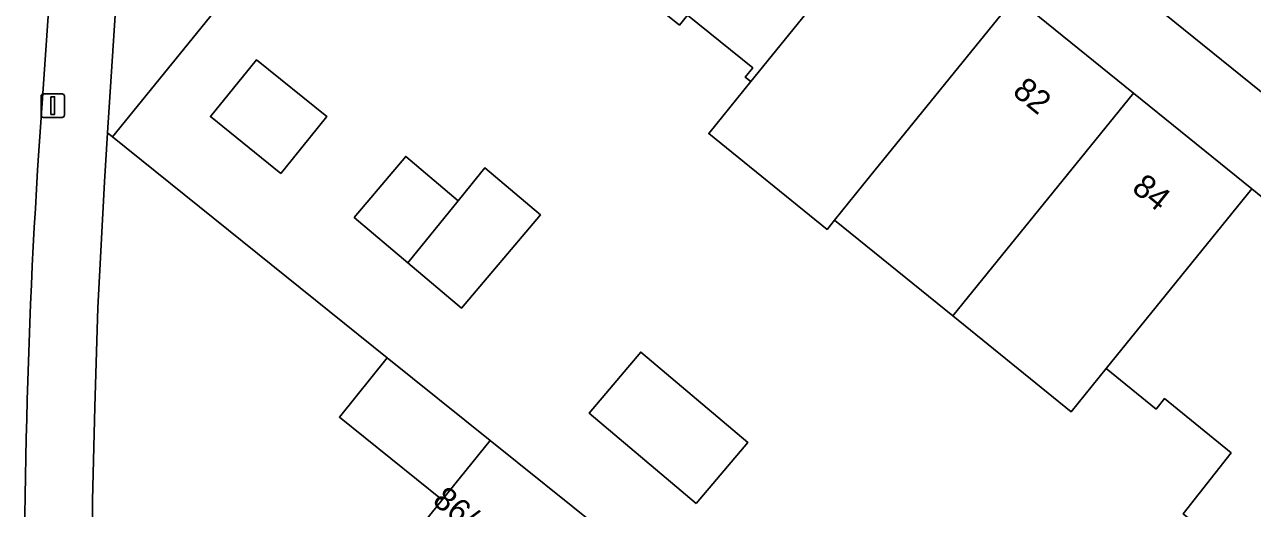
# Model space of a CAD drawing. Extents: x 160157 to 160921, y 381516 to 382045.
# Drawn here: x 160534.6 to 160586.6, y 381662.9 to 381683.4 of the extents above; entities that cross this region are included whole.
import ezdxf

# ---------------------------------------------------------------- set-up
doc = ezdxf.new("R2010")
doc.units = 0
for name, color, linetype in [('IMGEO_Erf', 7, 'Continuous'), ('IMGEO_Fietspad_gesloten', 7, 'Continuous'), ('IMGEO_Groenvoorziening', 7, 'Continuous'), ('IMGEO_Lichtmast', 7, 'Continuous'), ('IMGEO_Pand', 7, 'Continuous'), ('IMGEO_Pand_nummerreeks', 7, 'Continuous'), ('IMGEO_Voetpad_open', 7, 'Continuous')]:
    doc.layers.add(name, color=color, linetype=linetype)

msp = doc.modelspace()

# ---------------------------------------------------------------- linework, layer by layer
at = {"layer": 'IMGEO_Erf'}
for points in [[(160558.545, 381703.514), (160556.409, 381700.887), (160561.559, 381696.713), (160566.569, 381692.651), (160571.58, 381688.589), (160576.591, 381684.528), (160581.601, 381680.467), (160586.612, 381676.405), (160591.761, 381672.231), (160587.997, 381667.587), (160590.45, 381665.598), (160595.868, 381673.258), (160595.937, 381673.356), (160593.737, 381675.072)], [(160545.487, 381677.061), (160542.498, 381679.466), (160544.447, 381681.872), (160547.428, 381679.473), (160545.669, 381677.286)], [(160553.139, 381671.349), (160550.863, 381673.273), (160548.591, 381675.194), (160550.775, 381677.778), (160552.994, 381675.903), (160554.122, 381677.294), (160556.479, 381675.302)], [(160563.07, 381663.071), (160558.538, 381666.9), (160560.727, 381669.489), (160565.258, 381665.66)]]:
    msp.add_lwpolyline(points, close=True, dxfattribs=at)
for points in [[(160548.581, 381691.23), (160538.354, 381678.613), (160549.991, 381669.25), (160554.346, 381665.747), (160558.995, 381662.007)], [(160583.705, 381662.628), (160585.732, 381665.217), (160582.916, 381667.516), (160582.556, 381667.072), (160580.438, 381668.789), (160578.955, 381666.96), (160573.946, 381671.021), (160568.935, 381675.083), (160568.616, 381674.689), (160563.605, 381678.75), (160565.387, 381680.949), (160565.155, 381681.137), (160565.474, 381681.531), (160562.708, 381683.773), (160562.362, 381683.347), (160560.35, 381684.978)]]:
    msp.add_lwpolyline(points, dxfattribs=at)
at = {"layer": 'IMGEO_Fietspad_gesloten'}
msp.add_lwpolyline([(160535.403, 381680.442), (160536.908, 381702.404)], dxfattribs=at)
msp.add_arc((160815.535, 381659.561), 280.909, 175.73703, 181.03881, dxfattribs=at)
at = {"layer": 'IMGEO_Groenvoorziening'}
msp.add_lwpolyline([(160547.405, 381692.23), (160555.563, 381702.257), (160555.219, 381702.559), (160555.004, 381702.305), (160554.421, 381701.617), (160552.137, 381698.871), (160549.832, 381700.788), (160538.587, 381685.734), (160538.139, 381678.786), (160538.354, 381678.613), (160548.581, 381691.23)], close=True, dxfattribs=at)
msp.add_lwpolyline([(160549.075, 381659.196), (160552.321, 381663.23), (160547.966, 381666.733), (160549.991, 381669.25), (160538.354, 381678.613), (160538.139, 381678.786), (160538.007, 381676.697), (160537.734, 381671.359), (160537.596, 381667.162), (160537.509, 381663.201), (160537.482, 381658.369)], dxfattribs=at)
at = {"layer": 'IMGEO_Lichtmast'}
for p, q in [((160535.425, 381680.433), (160536.215, 381680.433)), ((160536.215, 381680.433), (160535.425, 381680.433)), ((160535.325, 381679.533), (160535.325, 381680.333)), ((160535.325, 381680.333), (160535.325, 381679.533)), ((160536.315, 381680.333), (160536.315, 381679.533)), ((160536.315, 381679.533), (160536.315, 381680.333)), ((160536.215, 381679.433), (160535.425, 381679.433)), ((160535.425, 381679.433), (160536.215, 381679.433))]:
    msp.add_line(p, q, dxfattribs=at)
msp.add_lwpolyline([(160535.745, 381680.308), (160535.895, 381680.308), (160535.895, 381679.558), (160535.745, 381679.558), (160535.745, 381680.308)], dxfattribs=at)
for centre, start, end in [((160535.425, 381680.333), 90, 180), ((160535.425, 381680.333), 90, 180), ((160536.215, 381680.333), 0, 90), ((160536.215, 381680.333), 360, 90), ((160535.425, 381679.533), 180, 270), ((160535.425, 381679.533), 180, 270), ((160536.215, 381679.533), 270, 0), ((160536.215, 381679.533), 270, 0)]:
    msp.add_arc(centre, 0.1, start, end, dxfattribs=at)
at = {"layer": 'IMGEO_Pand'}
for points in [[(160565.387, 381680.949), (160571.58, 381688.589), (160566.569, 381692.651), (160560.35, 381684.978), (160562.362, 381683.347), (160562.708, 381683.773), (160565.474, 381681.531), (160565.155, 381681.137)], [(160576.591, 381684.528), (160571.58, 381688.589), (160565.387, 381680.949), (160563.605, 381678.75), (160568.616, 381674.689), (160568.935, 381675.083), (160570.422, 381676.917)], [(160581.601, 381680.467), (160576.591, 381684.528), (160570.422, 381676.917), (160568.935, 381675.083), (160573.946, 381671.021), (160575.402, 381672.818)], [(160545.487, 381677.061), (160545.669, 381677.286), (160547.428, 381679.473), (160544.447, 381681.872), (160542.498, 381679.466)], [(160586.612, 381676.405), (160581.601, 381680.467), (160575.402, 381672.818), (160573.946, 381671.021), (160578.955, 381666.96), (160580.438, 381668.789)], [(160550.775, 381677.778), (160548.591, 381675.194), (160550.863, 381673.273), (160552.994, 381675.903)], [(160556.479, 381675.302), (160554.122, 381677.294), (160552.994, 381675.903), (160550.863, 381673.273), (160553.139, 381671.349)], [(160580.438, 381668.789), (160582.556, 381667.072), (160582.916, 381667.516), (160585.732, 381665.217), (160583.705, 381662.628), (160586.695, 381660.204), (160590.45, 381665.598), (160587.997, 381667.587), (160591.761, 381672.231), (160586.612, 381676.405)], [(160554.346, 381665.747), (160549.991, 381669.25), (160547.966, 381666.733), (160552.321, 381663.23)], [(160563.07, 381663.071), (160565.258, 381665.66), (160560.727, 381669.489), (160558.538, 381666.9)], [(160552.321, 381663.23), (160549.075, 381659.196), (160553.725, 381655.455), (160555.243, 381657.343), (160558.995, 381662.007), (160554.346, 381665.747)]]:
    msp.add_lwpolyline(points, close=True, dxfattribs=at)
at = {"layer": 'IMGEO_Voetpad_open'}
for points in [[(160537.941, 381717.089), (160537.542, 381711.422), (160541.907, 381710.232), (160543.445, 381709.83), (160543.445, 381709.818), (160543.894, 381709.696), (160548.601, 381708.54), (160553.856, 381707.249), (160554.79, 381706.968), (160554.92, 381706.877), (160553.214, 381704.852), (160552.116, 381703.534), (160554.421, 381701.617), (160555.004, 381702.305), (160555.219, 381702.559), (160555.563, 381702.257), (160547.405, 381692.23), (160548.581, 381691.23), (160550.289, 381693.337), (160556.409, 381700.887), (160558.545, 381703.514), (160593.737, 381675.072)], [(160543.445, 381709.818), (160543.445, 381709.83), (160541.907, 381710.232), (160537.542, 381711.422), (160536.908, 381702.404), (160535.403, 381680.442)], [(160539.804, 381624.471), (160539.268, 381628.112), (160539.1, 381629.573), (160538.905, 381631.265), (160538.494, 381635.504), (160538.166, 381639.708), (160537.881, 381644.095), (160537.582, 381652.686), (160537.482, 381658.369), (160537.509, 381663.201), (160537.596, 381667.162), (160537.734, 381671.359), (160538.007, 381676.697), (160538.139, 381678.786), (160538.587, 381685.734), (160539.125, 381693.597)]]:
    msp.add_lwpolyline(points, dxfattribs=at)
msp.add_arc((160815.535, 381659.561), 280.909, 175.73703, 181.03881, dxfattribs=at)

# ---------------------------------------------------------------- texts
at = {"layer": 'IMGEO_Pand_nummerreeks'}
for s, rotation, p in [('82', 320.9701, (160576.425, 381680.439)), ('84', 320.9701, (160581.478, 381676.344)), ('86/G08', 320.5776, (160551.856, 381663.101))]:
    msp.add_text(s, height=1, rotation=rotation, dxfattribs=at).set_placement(p)

doc.saveas('drawing.dxf')
